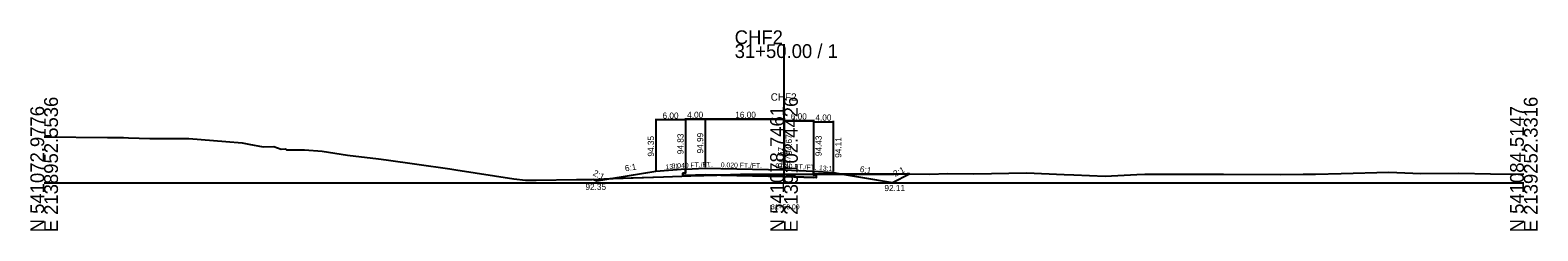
# Model space of a CAD drawing. Extents: x -12831 to 2303, y -10 to 39065.
# Drawn here: x 997.2 to 1302.8, y 2990.3 to 3031 of the extents above; entities that cross this region are included whole.
import ezdxf

# ---------------------------------------------------------------- set-up
doc = ezdxf.new("R2010")
doc.units = 0
for name, color, linetype in [('Level 5', 7, 'Continuous'), ('Level 53', 7, 'Continuous'), ('Level 54', 7, 'Continuous'), ('Level 55', 7, 'Continuous'), ('Level 7', 7, 'Continuous'), ('RD_GPK_XS_Cell', 7, 'Continuous'), ('RD_XS_EwShp', 7, 'Continuous'), ('RD_XS_ExGround', 7, 'Continuous'), ('RD_XS_Pave', 7, 'Continuous'), ('RD_XS_TX_Baseline', 7, 'Continuous'), ('RD_XS_TX_Ditch', 7, 'Continuous'), ('RD_XS_TX_Elev_EX', 7, 'Continuous'), ('RD_XS_TX_Elev_PR', 7, 'Continuous'), ('RD_XS_TX_Station', 7, 'Continuous')]:
    doc.layers.add(name, color=color, linetype=linetype)

msp = doc.modelspace()

# ---------------------------------------------------------------- linework, layer by layer
at = {"layer": 'Level 5'}
for p, q in [((1130, 3002), (1129.5, 3001.98)), ((1129.5, 3001.98), (1129.5, 3001.48)), ((1130, 3002.83), (1130, 3002)), ((1156, 3002.43), (1156, 3001.6)), ((1129.5, 3001.48), (1130, 3001.5)), ((1134, 3001.66), (1130, 3001.5)), ((1134, 3001.66), (1130, 3001.5)), ((1130, 3001.5), (1134, 3001.66)), ((1150, 3001.34), (1134, 3001.66)), ((1150, 3001.34), (1134, 3001.66)), ((1134, 3001.66), (1150, 3001.34)), ((1134, 3001.66), (1150, 3001.34)), ((1156, 3001.1), (1150, 3001.34)), ((1150, 3001.34), (1156, 3001.1)), ((1150, 3001.34), (1156, 3001.1)), ((1156, 3001.6), (1156.5, 3001.58)), ((1156.5, 3001.08), (1156, 3001.1)), ((1156.5, 3001.58), (1156.5, 3001.08))]:
    msp.add_line(p, q, dxfattribs=at)
at = {"layer": 'Level 54'}
for p, q in [((1124, 3012.98), (1124, 3002.55)), ((1130, 3012.78), (1124, 3012.78)), ((1130, 3013.14), (1130, 3003.03)), ((1130, 3013.14), (1130, 3003.03)), ((1130, 3013.14), (1130, 3003.03)), ((1130, 3012.98), (1130, 3003.03)), ((1130, 3012.94), (1134, 3012.94)), ((1130, 3012.94), (1134, 3012.94)), ((1134, 3012.94), (1130, 3012.94)), ((1134, 3013.14), (1134, 3003.19)), ((1134, 3013.14), (1134, 3003.19)), ((1134, 3013.14), (1134, 3003.19)), ((1134, 3013.14), (1134, 3003.19)), ((1134, 3013.14), (1134, 3003.19)), ((1134, 3013.14), (1134, 3003.19)), ((1134, 3013.14), (1134, 3003.19)), ((1134, 3012.94), (1150, 3012.94)), ((1134, 3012.94), (1150, 3012.94)), ((1150, 3012.94), (1134, 3012.94)), ((1150, 3012.94), (1134, 3012.94)), ((1150, 3013.14), (1150, 3002.87)), ((1150, 3013.14), (1150, 3002.87)), ((1150, 3013.14), (1150, 3002.87)), ((1150, 3013.14), (1150, 3002.87)), ((1150, 3012.82), (1150, 3002.87)), ((1150, 3012.82), (1150, 3002.87)), ((1150, 3012.82), (1150, 3002.87)), ((1150, 3012.62), (1156, 3012.62)), ((1156, 3012.62), (1150, 3012.62)), ((1156, 3012.62), (1150, 3012.62)), ((1156, 3012.82), (1156, 3002.63)), ((1156, 3012.82), (1156, 3002.63)), ((1156, 3012.82), (1156, 3002.63)), ((1156, 3012.58), (1156, 3002.63)), ((1156, 3012.38), (1160, 3012.38)), ((1160, 3012.58), (1160, 3002.31))]:
    msp.add_line(p, q, dxfattribs=at)
at = {"layer": 'Level 7'}
for p, q in [((1124, 3002.35), (1112, 3000.35)), ((1130, 3002.83), (1124, 3002.35)), ((1156, 3002.43), (1160, 3002.11)), ((1160, 3002.11), (1172, 3000.11)), ((1172, 3000.11), (1175.43, 3001.83)), ((1112, 3000.35), (1111.3, 3000.7))]:
    msp.add_line(p, q, dxfattribs=at)
at = {"layer": 'RD_GPK_XS_Cell'}
for p, q in [((1150, 3000), (1150, 3028.13)), ((1000, 3000), (1150, 3000)), ((1150, 3000), (1300, 3000))]:
    msp.add_line(p, q, dxfattribs=at)
at = {"layer": 'RD_XS_EwShp'}
for points in [[(1134, 3001.66), (1130, 3001.5), (1129.5, 3001.48), (1129.5, 3001.98), (1130, 3002), (1130, 3002.83), (1124, 3002.35), (1115.35, 3000.91), (1125.58, 3001.26), (1131.09, 3001.42), (1136.4, 3001.61)], [(1156.5, 3001.58), (1156.5, 3001.08), (1156, 3001.1), (1150, 3001.34), (1136.4, 3001.61), (1141.2, 3001.78), (1150, 3001.79), (1156, 3001.79), (1156, 3001.6)], [(1160, 3002.11), (1161.88, 3001.8), (1159.13, 3001.79), (1158.28, 3001.8), (1157.59, 3001.8), (1156.64, 3001.8), (1156, 3001.79), (1156, 3002.43)], [(1172, 3000.11), (1175.43, 3001.83), (1174.95, 3001.83), (1172.35, 3001.81), (1161.88, 3001.8)], [(1111.3, 3000.7), (1114.66, 3000.88), (1115.35, 3000.91), (1112, 3000.35)]]:
    msp.add_lwpolyline(points, close=True, dxfattribs=at)
at = {"layer": 'RD_XS_ExGround'}
for p, q in [((1000, 3009.37), (1000.07, 3009.38)), ((1000.07, 3009.38), (1012.83, 3009.23)), ((1012.83, 3009.23), (1016.11, 3009.19)), ((1016.11, 3009.19), (1017.07, 3009.17)), ((1017.07, 3009.17), (1021.39, 3009.05)), ((1021.39, 3009.05), (1026.91, 3008.99)), ((1026.91, 3008.99), (1029.35, 3009.02)), ((1029.35, 3009.02), (1036.84, 3008.42)), ((1036.84, 3008.42), (1040.11, 3008.12)), ((1040.11, 3008.12), (1041.49, 3007.87)), ((1041.49, 3007.87), (1044.42, 3007.3)), ((1044.42, 3007.3), (1046.54, 3007.42)), ((1046.54, 3007.42), (1048.04, 3006.87)), ((1048.04, 3006.87), (1048.89, 3006.95)), ((1048.89, 3006.95), (1049.14, 3006.75)), ((1049.14, 3006.75), (1049.32, 3006.74)), ((1049.32, 3006.74), (1052.75, 3006.74)), ((1052.75, 3006.74), (1056.38, 3006.42)), ((1056.38, 3006.42), (1061.47, 3005.64)), ((1061.47, 3005.64), (1067.77, 3004.88)), ((1067.77, 3004.88), (1069.32, 3004.67)), ((1069.32, 3004.67), (1075.54, 3003.8)), ((1075.54, 3003.8), (1082.27, 3002.87)), ((1082.27, 3002.87), (1083.44, 3002.68)), ((1083.44, 3002.68), (1095.21, 3000.85)), ((1150, 3001.79), (1156.64, 3001.8)), ((1156.64, 3001.8), (1157.59, 3001.8)), ((1157.59, 3001.8), (1158.28, 3001.8)), ((1158.28, 3001.8), (1159.13, 3001.79)), ((1159.13, 3001.79), (1172.35, 3001.81)), ((1172.35, 3001.81), (1174.95, 3001.83)), ((1174.95, 3001.83), (1179.55, 3001.82)), ((1179.55, 3001.82), (1183.16, 3001.92)), ((1183.16, 3001.92), (1188.5, 3001.85)), ((1188.5, 3001.85), (1199.17, 3002.05)), ((1199.17, 3002.05), (1206.82, 3001.71)), ((1223.16, 3001.79), (1234.29, 3001.82)), ((1234.29, 3001.82), (1236.36, 3001.81)), ((1236.36, 3001.81), (1239.08, 3001.78)), ((1255.28, 3001.76), (1257.77, 3001.81)), ((1257.77, 3001.81), (1262.97, 3001.9)), ((1262.97, 3001.9), (1272.64, 3002.22)), ((1272.64, 3002.22), (1279.09, 3001.95)), ((1279.09, 3001.95), (1286.85, 3002.02)), ((1286.85, 3002.02), (1293.26, 3001.86)), ((1293.26, 3001.86), (1298.21, 3001.82)), ((1298.21, 3001.82), (1300, 3001.83)), ((1095.21, 3000.85), (1097.59, 3000.59)), ((1097.59, 3000.59), (1099.76, 3000.6)), ((1099.76, 3000.6), (1107.92, 3000.68)), ((1107.92, 3000.68), (1111.09, 3000.69)), ((1111.09, 3000.69), (1114.66, 3000.88)), ((1114.66, 3000.88), (1125.58, 3001.26)), ((1125.58, 3001.26), (1131.09, 3001.42)), ((1131.09, 3001.42), (1141.2, 3001.78)), ((1141.2, 3001.78), (1150, 3001.79)), ((1206.82, 3001.71), (1208.73, 3001.65)), ((1208.73, 3001.65), (1215.14, 3001.38)), ((1215.14, 3001.38), (1221.51, 3001.72)), ((1221.51, 3001.72), (1223.16, 3001.79)), ((1239.08, 3001.78), (1250.75, 3001.74)), ((1250.75, 3001.74), (1255.28, 3001.76))]:
    msp.add_line(p, q, dxfattribs=at)
at = {"layer": 'RD_XS_Pave'}
for p, q in [((1130, 3002.83), (1134, 3002.99)), ((1134, 3002.99), (1150, 3002.67)), ((1150, 3002.67), (1156, 3002.43))]:
    msp.add_line(p, q, dxfattribs=at)

# ---------------------------------------------------------------- texts
at = {"layer": 'Level 53'}
for s, rotation, p in [('94.35', 90, (1123.63, 3005.35)), ('94.83', 90, (1129.63, 3005.83)), ('94.99', 90, (1133.62, 3005.99)), ('94.99', 90, (1133.62, 3005.99)), ('94.67', 90, (1151.62, 3005.67)), ('94.67', 90, (1151.62, 3005.67)), ('94.43', 90, (1157.63, 3005.43)), ('94.11', 90, (1161.63, 3005.11)), ('6:1', 9.4623, (1117.84, 3002.34)), ('6:1', 350.5377, (1165.3, 3002.24))]:
    msp.add_text(s, height=1.25, rotation=rotation, dxfattribs=at).set_placement(p)
msp.add_text('92.11', height=1.25, dxfattribs=at).set_placement((1170.36, 2998.36))
at = {"layer": 'Level 54'}
for s, p in [('6.00', (1125.37, 3013.03)), ('4.00', (1130.37, 3013.19)), ('4.00', (1130.37, 3013.19)), ('4.00', (1130.37, 3013.19)), ('16.00', (1140.12, 3013.19)), ('16.00', (1140.12, 3013.19)), ('16.00', (1140.12, 3013.19)), ('16.00', (1140.12, 3013.19)), ('6.00', (1151.37, 3012.87)), ('6.00', (1151.37, 3012.87)), ('6.00', (1151.37, 3012.87)), ('4.00', (1156.37, 3012.63))]:
    msp.add_text(s, height=1.25, dxfattribs=at).set_placement(p)
at = {"layer": 'Level 55'}
for s, height, rotation, p in [('2:1', 1.25, 333.4349, (1111.14, 3001.62)), ('13:1', 1, 4.5739, (1126.03, 3002.76)), ('0.040 FT./FT.', 1, 2.2906, (1127.22, 3002.97)), ('0.040 FT./FT.', 1, 2.2906, (1127.22, 3002.97)), ('0.040 FT./FT.', 1, 2.2906, (1127.22, 3002.97)), ('0.020 FT./FT.', 1, 358.8542, (1137.18, 3003.18)), ('0.020 FT./FT.', 1, 358.8542, (1137.18, 3003.18)), ('0.020 FT./FT.', 1, 358.8542, (1137.18, 3003.18)), ('0.020 FT./FT.', 1, 358.8542, (1137.18, 3003.18)), ('0.040 FT./FT.', 1, 357.7094, (1148.24, 3002.99)), ('0.040 FT./FT.', 1, 357.7094, (1148.24, 3002.99)), ('0.040 FT./FT.', 1, 357.7094, (1148.24, 3002.99)), ('13:1', 1, 355.4261, (1157.07, 3002.6)), ('2:1', 1.25, 26.5651, (1172.54, 3001.22))]:
    msp.add_text(s, height=height, rotation=rotation, dxfattribs=at).set_placement(p)
at = {"layer": 'RD_GPK_XS_Cell'}
for s, p in [('CHF2', (1140, 3028.13)), ('31+50.00 / 1', (1140, 3025.33))]:
    msp.add_text(s, height=2.8, dxfattribs=at).set_placement(p)
for s, p in [('E 2138952.5536', (1002.8, 2990)), ('E 2139102.4426', (1152.8, 2990)), ('E 2139252.3316', (1302.8, 2990)), ('N 541072.9776', (1000, 2990)), ('N 541078.7461', (1150, 2990)), ('N 541084.5147', (1300, 2990))]:
    msp.add_text(s, height=2.8, rotation=90, dxfattribs=at).set_placement(p)
at = {"layer": 'RD_XS_TX_Baseline'}
msp.add_text('CHF2', height=1.5, dxfattribs=at).set_placement((1147.31, 3016.67))
at = {"layer": 'RD_XS_TX_Ditch'}
msp.add_text('92.35', height=1.25, dxfattribs=at).set_placement((1109.74, 2998.6))
at = {"layer": 'RD_XS_TX_Elev_EX'}
msp.add_text('93.79', height=1, rotation=90, dxfattribs=at).set_placement((1151.25, 3002.79))
at = {"layer": 'RD_XS_TX_Elev_PR'}
msp.add_text(' 94.67', height=1.25, rotation=90, dxfattribs=at).set_placement((1150, 3002.67))
at = {"layer": 'RD_XS_TX_Station'}
msp.add_text('31+50.00', height=1, dxfattribs=at).set_placement((1147.36, 2994.67))

doc.saveas('drawing.dxf')
